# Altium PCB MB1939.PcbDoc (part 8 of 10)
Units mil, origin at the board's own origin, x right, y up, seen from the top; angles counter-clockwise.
Board outline 5910.64 x 4335.93 mil, 6 copper layers (Top Layer, l2_GND, L3_SIG, L4_VCC, L5_GND, Bottom Layer), stack 58.424 mil thick; 635 components, 489 nets, 2289 pads, 1388 vias.
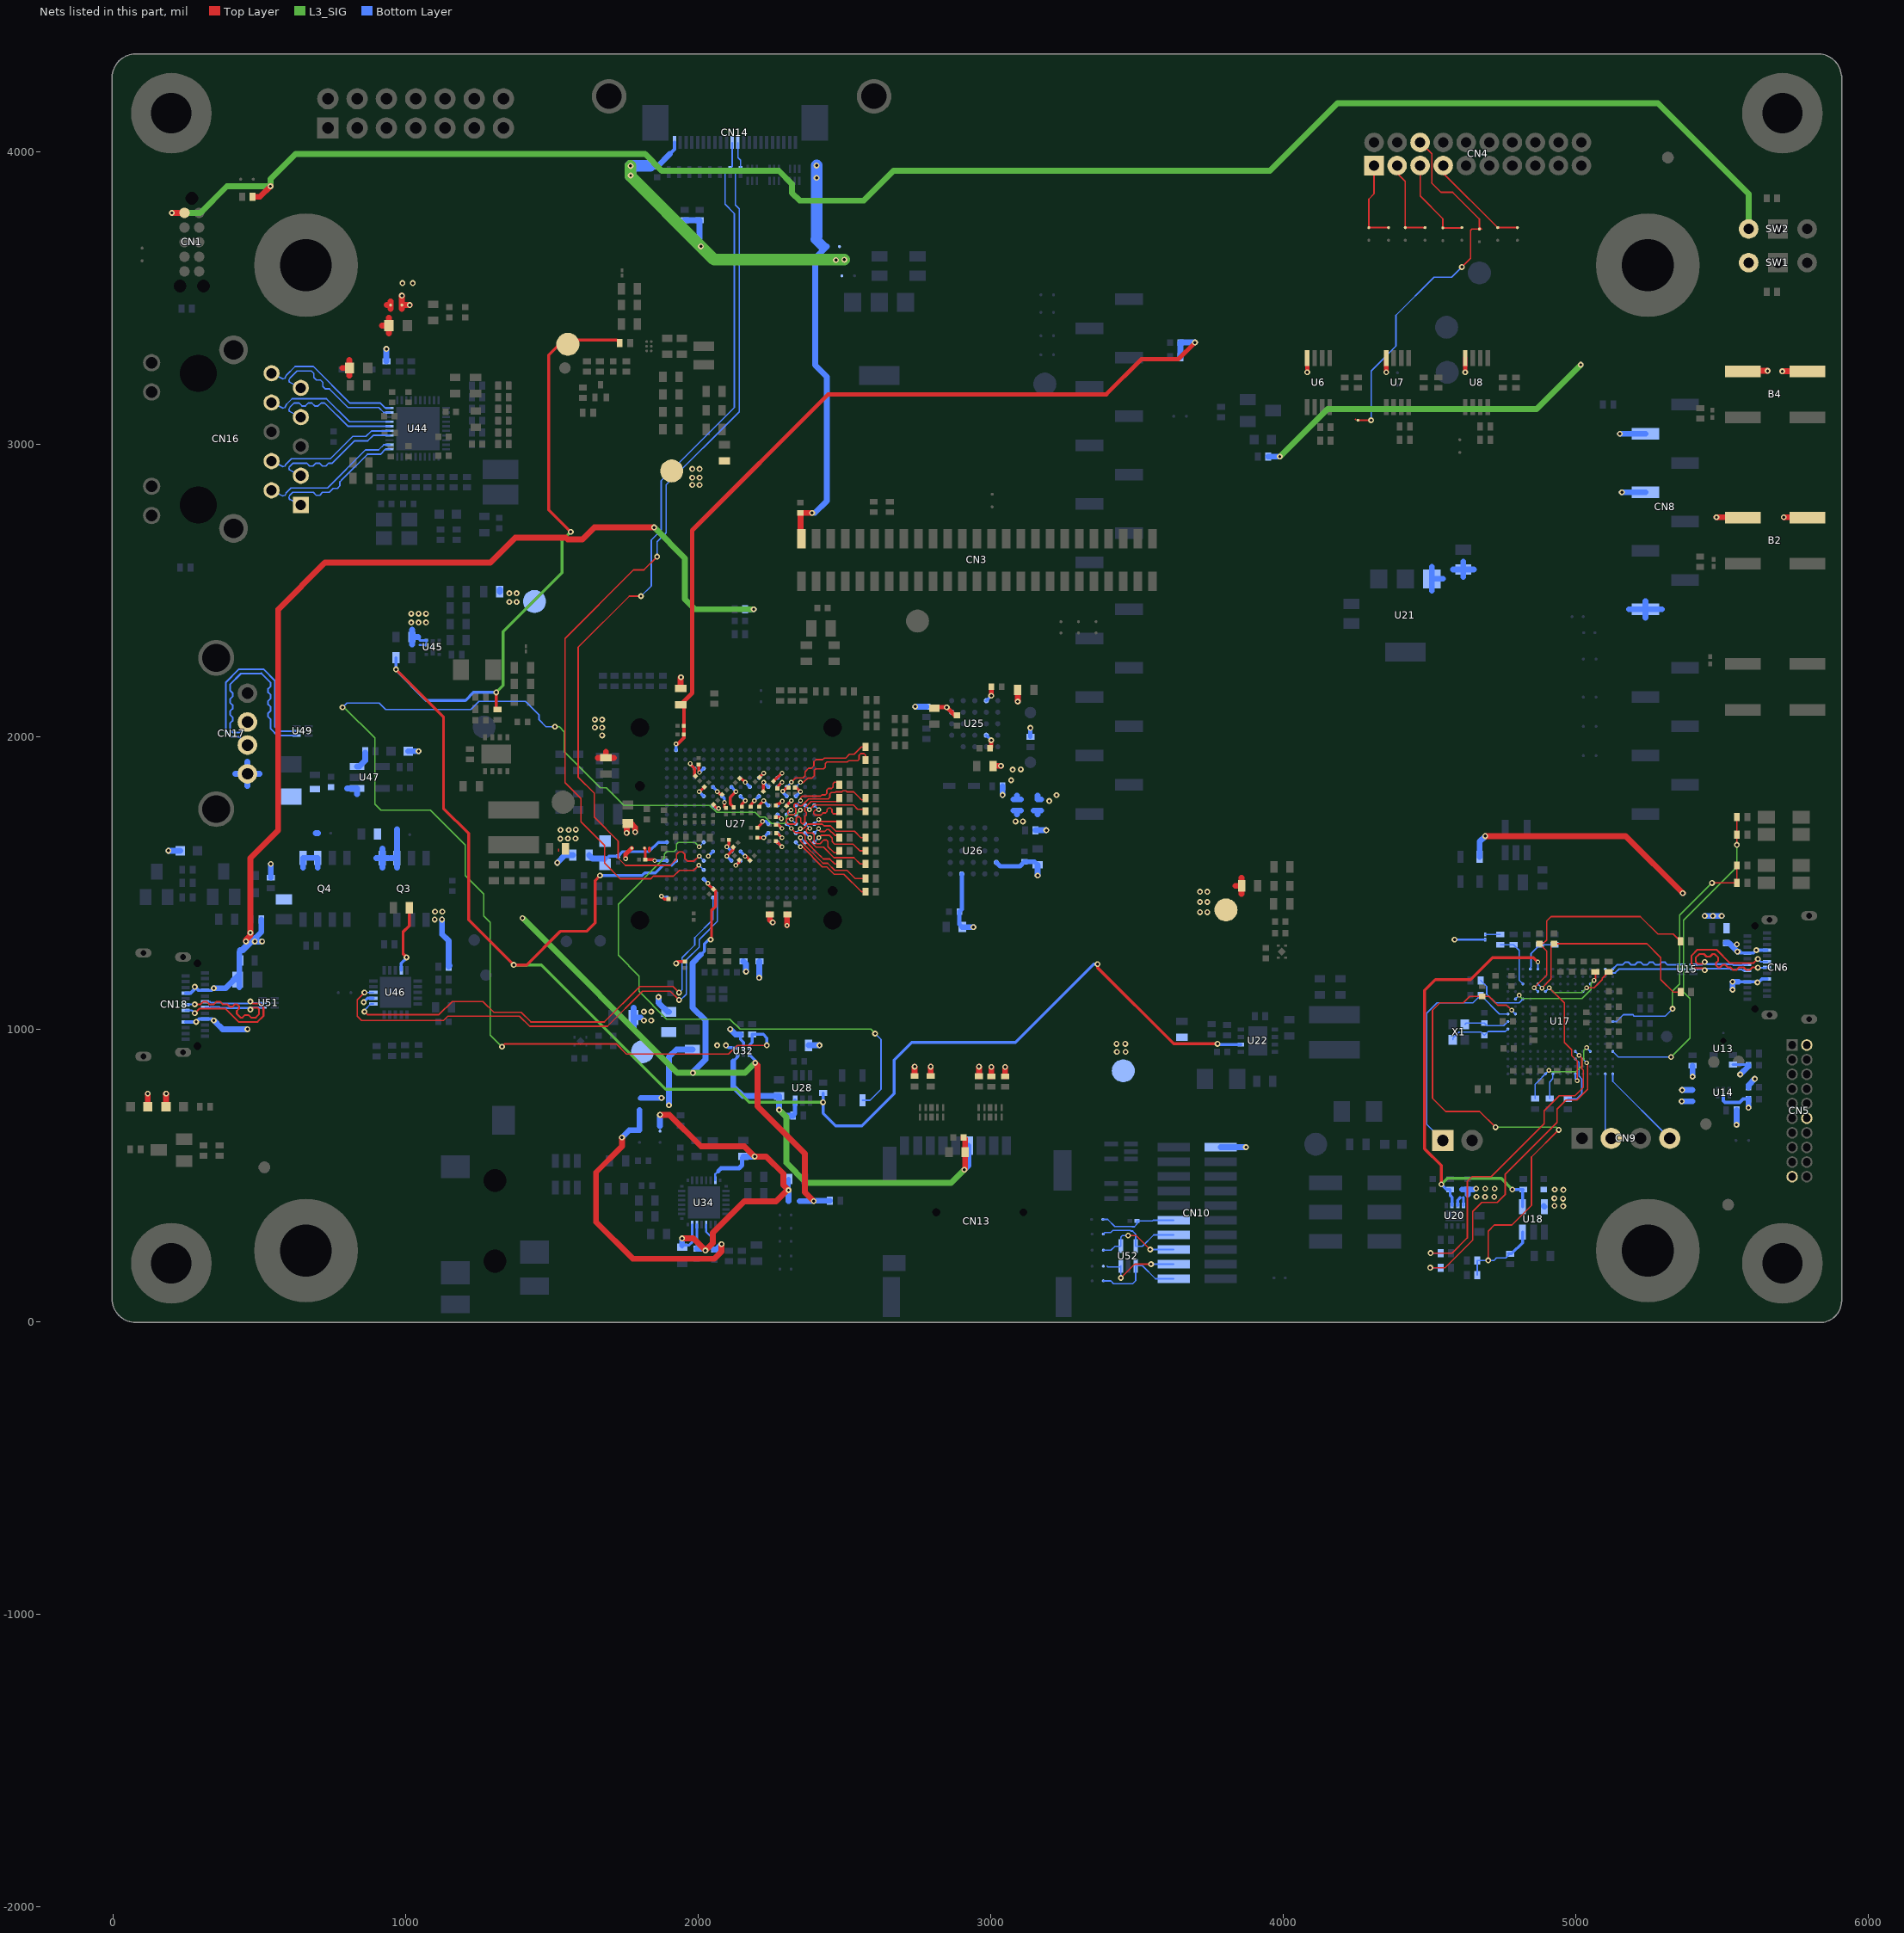
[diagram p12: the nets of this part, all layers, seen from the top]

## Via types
v1: diameter 20, hole 10, Top Layer to Bottom Layer, tented both sides, 1072 vias
v2: diameter 16, hole 8, Top Layer to Bottom Layer, tented both sides, 316 vias

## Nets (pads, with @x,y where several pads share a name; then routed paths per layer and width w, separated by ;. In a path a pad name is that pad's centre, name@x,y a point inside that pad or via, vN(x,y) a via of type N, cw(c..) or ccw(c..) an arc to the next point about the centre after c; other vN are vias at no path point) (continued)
PO5: R150.2 U27.K15 U32.6 | length 4418
  Top Layer w5: v1(1330,940) 1340,950 1720,950 1755,915 2104,915 2134,945 v1(2235,945)
  L3_SIG w4: v1(785,2100) 790,2100 895,1995 895,1770 915.73,1749.27 1085.73,1749.27 1205,1630 1205,1525 1268,1462 1268,1387 1290,1365 1290,980 v1(1330,940) ; v1(1511,2034) 1526,2034 1543,2017 1543,1948.37 1665.68,1825.69 1686.31,1825.69 1747,1765 2040,1765 2064,1741 2194.9,1741 2210.9,1725 2229,1725 2251,1703 2295.46,1703 2301.46,1709 2301.46,1726.13 2309.33,1734 2334.76,1734 v2(2349.15,1748.39)
  Bottom Layer w5: v1(785,2100) 800,2115 910,2115 932.5,2092.5 1223.9,2092.5 1251.9,2120.5 1409.8,2120.5 1456.75,2073.55 1456.75,2057.25 1480,2034 v1(1511,2034) ; U27.K15@2334.32,1733.56 v2(2349.15,1748.39)
  Bottom Layer w10: U32.6@2174.67,936.81 2174.67,944.67 2185,955 R150.2@2185,982.28 2222.72,982.28 2235,970 v1(2235,945)
PP0: R56.2 U27.G17 | length 213.9
  Top Layer w5: v2(2412.97,1654.77) 2421.2,1663 2448,1663 2458,1653 2458,1640.99 2466.36,1632.63 2529.52,1632.63 2545.87,1616.28 2546.16,1616.28 2552.44,1610 R56.2@2572.29,1610
  Bottom Layer w5: U27.G17@2397.32,1639.02 2397.31,1639.11 v2(2412.97,1654.77)
PP1: R55.2 U27.H16 | length 256.8
  Top Layer w5: v2(2381.51,1654.79) 2381.51,1643.49 2403,1622 2428.53,1622 2464.25,1586.28 2532.72,1586.28 2554,1565 R55.2@2572.29,1565
  Bottom Layer w5: U27.H16@2365.82,1670.51 v2(2381.51,1654.79)
PP2: R47.2 U27.J17 | length 98.2
  Top Layer w5: v2(2412.14,1716.9) 2419.04,1710 2472.28,1710 R47.2@2482.29,1700
  Bottom Layer w5: U27.J17@2397.32,1702.01 2412.14,1716.84 v2(2412.14,1716.9)
PP3: R45.2 U27.J16 | length 220.5
  Top Layer w5: v2(2381.51,1686.29) 2375.04,1686.29 2370.04,1681.29 2370.04,1675.79 2375.04,1670.79 2391.21,1670.79 2397,1665 2397,1642.01 2404.5,1634.51 2417,1634.51 2429.2,1646.71 2439,1646.71 2444,1641.71 2444,1624 2465,1603 2475.28,1603 R45.2@2482.29,1610
  Bottom Layer w5: U27.J16@2365.82,1702.01 v2(2381.51,1686.29)
PP4: R57.2 U27.H15 | length 269.5
  Top Layer w5: v2(2349.55,1685.79) 2359.79,1685.79 2374.79,1700.79 2424.22,1700.79 2430.01,1695 2452,1695 2470.72,1676.28 2535,1676.28 2556.28,1655 R57.2@2572.29,1655
  Bottom Layer w5: U27.H15@2334.32,1670.56 v2(2349.55,1685.79)
PP5: R44.2 U27.J14 | length 246.8
  Top Layer w5: v2(2318.52,1686.3) 2333.53,1671.29 2356.24,1671.29 2365.52,1662.01 2365.52,1643.99 2416.51,1593 2417.01,1593 2427.99,1582.02 2450,1582.02 2467.02,1565 R44.2@2482.29,1565
  Bottom Layer w5: U27.J14@2302.83,1702.01 v2(2318.52,1686.3)
PP6: R54.2 U27.G16 | length 308.9
  Top Layer w5: v2(2349.99,1654.73) 2349.99,1643.83 2426.81,1567.01 2443,1567.01 2467.01,1543 2509,1543 2537,1515 R54.2@2572.29,1515
  Bottom Layer w5: v2(2349.99,1654.73) 2365.7,1639.02 U27.G16@2365.82,1639.02
PP7: R53.2 U27.G15 | length 308
  Top Layer w5: v2(2350.02,1623.29) 2356.7,1623.29 2424.99,1555 2440,1555 2465,1530 2498,1530 2558,1470 R53.2@2572.29,1470
  Bottom Layer w5: U27.G15@2334.33,1639.02 v2(2350.02,1623.29)
PP8: R59.2 U27.L16 | length 228.2
  Top Layer w5: v2(2380.64,1750.11) 2396.78,1766.25 2504.54,1766.25 ; 2504.57,1766.28 2531.16,1766.28 2545.44,1752 2565.28,1752 R59.2@2572.29,1745
  Bottom Layer w5: U27.L16@2365.82,1765 2365.82,1764.93 v2(2380.64,1750.11)
PP9: R64.2 U27.N14 | length 342
  Top Layer w5: v2(2318.91,1844.34) 2319.16,1844.34 2333.83,1859.01 2358,1859.01 2365.52,1866.53 2365.52,1880.01 2377.39,1891.88 2386.45,1891.88 2386.83,1892.26 2387.47,1892.26 2395.96,1900.75 2395.96,1913.95 2403.27,1921.26 2426.25,1921.26 2431.99,1927 2504.5,1927 2517.5,1940 2533,1940 2558,1965 R64.2@2572.29,1965
  Bottom Layer w5: U27.N14@2302.83,1827.99 2318.91,1844.09 v2(2318.91,1844.34)
PP10: R63.2 U27.N15 | length 330
  Top Layer w5: v2(2350.02,1843.7) 2359.32,1843.7 2363.32,1847.7 2374.32,1858.01 2375.19,1858.01 2375.45,1858.27 2389.27,1858.27 2397.52,1866.52 2397.52,1885 2402.52,1890 2429,1890 2435,1896 2435,1908 2440,1913 2510,1913 2515,1918 2546,1918 2550.11,1922.11 2550.11,1935.89 2556.22,1942 2567.28,1942 2572.28,1937 R63.2@2572.29,1920
  Bottom Layer w5: U27.N15@2334.33,1827.99 v2(2350.02,1843.7)
PP11: R50.2 U27.L15 | length 206.5
  Top Layer w5: v2(2350.24,1780.98) 2350.24,1791.38 2355.25,1796.39 2418.38,1796.39 2422.99,1801 2435,1801 2440,1806 2440,1818 2445,1823 2455.99,1823 2460.99,1828 2460.99,1839 2466.09,1844.1 2477.28,1844.1 2482.28,1839.1 R50.2@2482.29,1835
  Bottom Layer w5: U27.L15@2334.33,1765 2334.32,1765.06 v2(2350.24,1780.98)
PP12: R49.2 U27.J15 | length 346.3
  Top Layer w5: v2(2319.14,1717.13) 2316.1,1720.17 2306.46,1720.17 2301.46,1715.17 2301.46,1706 2306.46,1701 2331,1701 2335.46,1705.46 2335.46,1722.54 2338.92,1726 2346,1726 2351,1721 2351,1706.66 2355,1702.66 2360.66,1702.66 2365,1707 2365,1728 2369.96,1732.96 2369.96,1740.04 2365,1745 2365,1756.49 2386.52,1778.01 2477.28,1778.01 2482.28,1783.01 R49.2@2482.29,1790
  Bottom Layer w5: v2(2319.14,1717.13) U27.J15@2334.33,1702.01 U27.J15@2334.33,1702.01
PP13: R60.2 U27.K14 | length 396.1
  Top Layer w5: v2(2317.65,1748.39) 2311.47,1748.39 2306.92,1743.84 2306.92,1737.41 2311.46,1732.87 2329,1732.87 2334,1737.87 2334,1754.01 2328.05,1759.96 2328.05,1767.05 2331.96,1770.96 2339.04,1770.96 2346.45,1763.55 2353.54,1763.55 2377,1787.01 2445,1787.01 2450,1792.01 2450,1804 2455,1809 2468.08,1809 2470.36,1811.28 2491.28,1811.28 2495,1815 2505,1815 2508.72,1811.28 2531.71,1811.28 2554,1788.99 2554,1788.91 2559.01,1783.9 2567.28,1783.9 2572.28,1788.9 R60.2@2572.29,1790
  Bottom Layer w5: U27.K14@2302.82,1733.56 v2(2317.65,1748.39)
PP14: R48.2 U27.L17 | length 170.5
  Top Layer w5: v2(2412.14,1750.11) 2401.95,1750.11 2395.46,1743.62 2395.46,1736.54 2400,1732 2420,1732 2427,1739 2435.69,1739 2440.67,1743.98 2440.67,1751.02 2445.65,1756 2452.69,1756 2457.67,1751.02 2457.67,1741 2462.67,1736 2477.28,1736 2482.28,1741 R48.2@2482.29,1745
  Bottom Layer w5: U27.L17@2397.32,1765 2397.31,1764.94 v2(2412.14,1750.11)
PP15: R46.2 U27.H17 | length 111.7
  Top Layer w5: v2(2411.98,1685.24) 2411.98,1681.16 2416.99,1676.15 2433.15,1676.15 2439.96,1682.96 2447.04,1682.96 2467,1663 2474.28,1663 R46.2@2482.29,1655
  Bottom Layer w5: U27.H17@2397.32,1670.51 2397.31,1670.57 v2(2411.98,1685.24)
PQ0: CN14.12 U27.E5 U35.1 | length 3142.1
  Top Layer w5: v1(1805,2480) 1765,2480 1590,2305 1590,1861.66 1645,1806.66 1645,1725 1727.08,1642.92 1727.08,1584.92 1752,1560 1905.01,1560 1926.1,1581.09 1926.1,1597.83 1934.59,1606.32 1946.61,1606.32 1955.1,1597.83 1955.1,1582.62 1962.9,1574.82 1986.83,1574.82 v2(2003.7,1591.69)
  Bottom Layer w5: v1(1805,2480) 1840,2515 1840,2672 1874,2706 1874,2875 2124,3125 2124,3788.02 2092.02,3820 2092.02,3925.89 2092.5,3926.37 2092.5,3932.5 2102.3,3942.3 U35.1@2110,3942.31 2116.46,3948.76 CN14.12@2116.46,4030.71 ; v2(2003.7,1591.69) U27.E5@2019.36,1576.03
PQ5: CN14.11 U27.D5 U33.1 | length 3191.2
  Top Layer w5: v1(1860,2615) 1815,2570 1780,2570 1545,2335 1545,1843 1600,1788 1600,1709 1680.78,1628.22 1680.78,1567.56 1734.34,1514 1838,1514 1847,1523 1916.19,1523 1936.19,1543 1938.01,1543 1938.31,1543.3 1985.31,1543.3 v2(2002.95,1560.94)
  Bottom Layer w5: v1(1860,2615) 1860,2666 1891,2697 1891,2861 2140.5,3110.5 2140.5,3804.16 2127.76,3816.9 2127.76,3926.63 2137.33,3936.2 2140,3936.2 2145,3941.2 U33.1@2145,3942.31 2145,3970 2136.14,3978.86 CN14.11@2136.15,4030.71 ; v2(2002.95,1560.94) U27.D5@2019.36,1544.53
PQ7: D5.2 U27.G5 | length 1880.9
  L3_SIG w4: v2(2003.59,1623.23) 1988.82,1638 1932,1638 1926,1632 1926,1615 1919,1608 1893.86,1608 1885,1599.14 1885,1585 1727.1,1427.1 1727.1,1252.9 1798,1182 1798,1130.03 1893.03,1035 2108.02,1035 2143.02,1000 2590,1000 v1(2605,985)
  Bottom Layer w5: v2(2003.59,1623.23) U27.G5@2019.36,1639.02 ; D5.2@2562.01,757.36 2587.37,757.36 2625,794.99 2625,965 v1(2605,985)
PWR_ON: R12.1 R25.1 R144.1 R199.1 TP11.1 U22.2 U27.E2 | length 7204.2
  Top Layer w10: v1(967.44,2230) 1130,2067.44 1130,1755 1216,1669 1216,1374 v1(1370,1220) 1415,1220 1530,1335 1620,1335 1648,1363 1648,1508 v1(1665,1525) ; v1(1310,2151) 1310,2097.72 R12.1@1315,2092.72 ; v1(1565,2700) 1490,2775 1490,3304 1541,3355 1722.28,3355 R25.1@1732.28,3345 ; v1(3365,1222.5) 3365,1210 3625,950 v1(3775,950)
  L3_SIG w10: v1(1310,2151) 1334,2175 1334,2359 1535,2560 1535,2670 v1(1565,2700) ; v1(1370,1220) 1465,1220 1890,795 2130,795 2175,750 v1(2427.01,750)
  Bottom Layer w8: 1875,1555 1880.62,1560.62 1909.46,1560.62
  Bottom Layer w10: R199.1@967.45,2270 v1(967.44,2230) 967.44,2227.56 1071,2124 1205.2,2124 1232.2,2151 v1(1310,2151) ; v1(1665,1525) 1809,1525 1818,1534 1854,1534 1875,1555 ; 1909.46,1560.62 U27.E2@1924.88,1576.03 ; R144.1@2427.01,781.77 v1(2427.01,750) 2427.01,712.99 2470,670 2560,670 2670,780 2670,895 2730,955 3085,955 3352.5,1222.5 v1(3365,1222.5) ; v1(3775,950) 3777.29,947.71 U22.2@3854.92,947.71
RJ45_D1_N: CN16.2 U44.2 | length 482.1
  Bottom Layer w5.1: CN16.2@542.49,2841.8 581.2,2822.44 588.05,2824.73 592.35,2833.36 608.99,2850 733.78,2850 863.78,2980 908.27,2980 925.98,2997.71 U44.2@946.18,2997.71
RJ45_D1_P: CN16.1 U44.1 | length 480.7
  Bottom Layer w5.1: CN16.1@642.49,2791.8 603.73,2811.18 601.47,2818.02 604.69,2824.47 615.21,2834.99 685.2,2835 695,2825.2 707,2825.2 716.8,2835 740,2835 753.52,2848.52 767.39,2848.52 775.88,2857.01 775.88,2870.88 784.36,2879.36 ; 784.39,2879.36 870,2965 914.49,2965 931.45,2981.96 U44.1@946.18,2981.96
RJ45_D2_N: CN16.4 U44.5 | length 459.6
  Bottom Layer w5.1: CN16.4@542.49,2941.8 581.2,2922.44 588.05,2924.73 590.84,2930.33 610.11,2949.6 743.48,2949.6 819.98,3026.1 865.32,3026.1 883.79,3044.57 945.78,3044.57 U44.5@946.18,3044.96
RJ45_D2_P: CN16.3 U44.4 | length 458.5
  Bottom Layer w5.1: CN16.3@642.49,2891.8 603.73,2911.18 601.47,2918.02 603.18,2921.45 616.33,2934.6 662.5,2934.6 672.3,2924.8 684.3,2924.8 694.1,2934.6 706.1,2934.6 715.9,2924.8 727.9,2924.8 737.7,2934.6 749.7,2934.6 826.2,3011.1 871.54,3011.1 890.01,3029.57 945.81,3029.57 U44.4@946.18,3029.21
RJ45_D3_N: CN16.8 U44.7 | length 456.3
  Bottom Layer w5.1: CN16.8@542.49,3141.8 581.2,3122.44 588.05,3124.73 593.55,3135.76 612.79,3155 730,3155 808.93,3076.07 921.24,3076.07 921.62,3076.45 U44.7@946.17,3076.45
RJ45_D3_P: CN16.7 U44.6 | length 455.2
  Bottom Layer w5.1: CN16.7@642.49,3091.8 603.73,3111.18 601.47,3118.02 605.89,3126.87 619.01,3140 636.58,3140 646.38,3130.2 658.38,3130.2 668.18,3140 680.18,3140 689.98,3130.2 701.98,3130.2 711.78,3140 723.78,3140 802.71,3061.07 921.24,3061.07 921.61,3060.7 U44.6@946.18,3060.7
RJ45_D4_N: CN16.10 U44.10 | length 486
  Bottom Layer w5.1: CN16.10@542.49,3241.8 581.2,3222.44 588.05,3224.73 593.33,3235.32 623.01,3265 685,3265 810.09,3139.91 915.08,3139.91 931.29,3123.7 U44.10@946.18,3123.7
RJ45_D4_P: CN16.9 U44.9 | length 485.3
  Bottom Layer w5.1: CN16.9@642.49,3191.8 603.73,3211.18 601.47,3218.02 605.67,3226.43 629.23,3250 678.78,3250 687.26,3241.52 687.26,3227.65 695.75,3219.17 709.61,3219.17 718.09,3210.69 718.09,3196.82 726.58,3188.34 740.44,3188.34 803.87,3124.91 908.86,3124.91 925.82,3107.95 U44.9@946.18,3107.95
STLK_LED: R100.2 R101.1 U17.D15 | length 1138.5
  Top Layer w5: v1(5550,1630) R101.1@5550.01,1725
  L3_SIG w4: v1(5325,905) 5390,970 5390,1105 5368,1127 5368,1373 5550,1555 v1(5550,1630)
  Bottom Layer w5: U17.D15@5125.83,924.06 5144.88,905 v1(5325,905)
STLK_NRST: C130.2 JP1.1 U17.J1 | length 787.5
  Bottom Layer w5: JP1.1@4545,620 4490,675 4490,1055 4525,1090 4647.99,1090 C130.2@4674.41,1116.42 4738.82,1052.01 U17.J1@4767.56,1052.01
STLK_OSC_IN: C127.1 U17.G1 X1.1 | length 216.2
  Bottom Layer w5: X1.1@4579.34,963.42 4579.33,969.33 4600,990 4675.83,990 C127.1@4686.69,979.14 4699.94,992.39 4759.12,992.39 U17.G1@4767.56,1000.83
STLK_OSC_OUT: C128.2 U17.H1 X1.3 | length 158.1
  Bottom Layer w5: X1.3@4620.67,1016.57 4625.08,1020.98 C128.2@4686.69,1020.98 4695.28,1012.39 4753.53,1012.39 U17.H1@4767.56,1026.42
STLK_SWCLK: CN9.2 U17.A14 | length 228.7
  Bottom Layer w5: U17.A14@5100.24,847.29 5100.23,647.29 CN9.2@5120.51,627.01
STLK_SWDIO: CN9.4 U17.A15 | length 300.9
  Bottom Layer w5: U17.A15@5125.83,847.29 5125.82,821.7 CN9.4@5320.51,627.01
STLK_UCPD_CC1_C: C103.1 R96.1 U17.M5 | length 791.1
  Top Layer w5: v2(4856.85,1141.85) 4900,1185 4900,1267.28 C103.1@4875,1292.28 4887.28,1292.28 4900,1305 4900,1370 4915,1385 5220,1385 5280,1325 5332.28,1325 R96.1@5357.29,1300
  Bottom Layer w5: v2(4856.85,1141.85) U17.M5@4869.92,1128.78
STLK_UCPD_CC2_C: C105.1 R97.1 U17.N5 | length 734
  Top Layer w5: v2(4883.54,1140.75) 4915,1172.21 4915,1283.78 4923.5,1292.28 5242.72,1292.28 5290,1245 5290,1170 5332.99,1127.01 R97.1@5357.8,1127.01
  Bottom Layer w5: U17.N5@4869.92,1154.37 v2(4883.54,1140.75)
STLK_USB_CN_N: CN6.A7 CN6.B7 U15.2 | length 567.7
  Top Layer w6.1: v1(5440,1202) 5433.5,1208.5 5409.88,1208.5 5395,1223.38 5395,1251.74 5415.26,1272 5479.91,1272 5525.41,1226.5 5607.74,1226.5 v1(5621.35,1240.11)
  Bottom Layer w6.1: U15.2@5401.67,1205 5402.42,1205.75 5436.25,1205.75 v1(5440,1202) 5445.39,1207.39 5527.61,1207.39 5531.32,1203.68 5566.78,1203.68 5569.12,1201.33 CN6.A7@5585.95,1201.33 ; v1(5621.35,1240.11) 5629.4,1232.06 5630.44,1232.06 5631.64,1230.86 CN6.B7@5652.88,1230.86
STLK_USB_CN_P: CN6.A6 CN6.B6 U15.1 | length 567.4
  Top Layer w6.1: v1(5440,1230) 5433.5,1223.5 5416.1,1223.5 5410,1229.6 5410,1245.53 5421.47,1257 5437.3,1257 5446.1,1248.2 5458.1,1248.2 5466.9,1257 5473.7,1257 5486.32,1244.38 5486.32,1234.29 5478.51,1226.48 5478.51,1218.12 5484.61,1212.02 5493.25,1212.02 5501.36,1220.13 5510.57,1220.13 5519.2,1211.5 5527.61,1211.5 5536.41,1202.7 5548.41,1202.7 5557.21,1211.5 5573.04,1211.5 5581.84,1202.7 5593.84,1202.7 5602.64,1211.5 5619.96,1211.5 v1(5621.35,1210.11)
  Bottom Layer w6.1: U15.1@5401.67,1220.75 5430.75,1220.75 v1(5440,1230) 5447.61,1222.39 5533.82,1222.39 5537.54,1218.68 5566.78,1218.68 5569.12,1221.02 CN6.A6@5585.95,1221.02 ; v1(5621.35,1210.11) 5651.81,1210.11 CN6.B6@5652.88,1211.18
STLK_USB_N: U15.5 U17.R14 | length 270.7
  Bottom Layer w6.1: U17.R14@5100.23,1205.55 5113.21,1192.57 5134.06,1192.57 5146.49,1205 5360.08,1205 U15.5@5360.33,1205.25
STLK_USB_P: U15.6 U17.R15 | length 270
  Bottom Layer w6.1: U17.R15@5125.82,1205.55 5140.27,1220 5159.2,1220 5168,1228.8 5180,1228.8 5188.8,1220 5200.8,1220 5209.6,1228.8 5221.6,1228.8 5230.4,1220 5242.4,1220 5251.2,1228.8 5263.2,1228.8 5272,1220 5284,1220 5292.8,1228.8 5304.8,1228.8 5313.6,1220 5359.58,1220 U15.6@5360.33,1220.75
STLK_VCP_RX: R112.1 U17.C10 | length 183.6
  Bottom Layer w5: R112.1@4971.69,761.42 5001.41,761.42 5020,780.01 5020,830 5010,840 5010,886.34 U17.C10@4997.88,898.47
STLK_VCP_TX: R114.1 U17.A7 | length 89.2
  Bottom Layer w5: R114.1@4910,762.72 4910,819.99 4921.1,831.09 U17.A7@4921.1,847.29
STMOD_ADC: CN4.13 SB9.2 SB16.1 | length 1317.2
  Top Layer w4: CN4.13@4467.52,4030.71 4506.9,3991.33 4506.9,3892.1
  Top Layer w5: 4245.51,3083.39 4247.12,3085 ; SB9.2@4255,3081.38 v1(4300,3081.38) ; 4506.9,3892.1 4538.6,3860.4 4578.6,3860.4 4669.8,3769.2 4669.8,3742 4677.12,3734.68 4644.68,3734.68 4640,3730 4640,3635 v1(4610,3605)
  Bottom Layer w5: v1(4300,3081.38) 4300,3250 4385,3335 4385,3440 4515,3570 4575,3570 v1(4610,3605)
STMOD_MISO5/RX: CN4.3 SB14.2 SB15.2 | length 285.3
  Top Layer w5: CN4.3@4467.52,3926.26 4467.52,3847.48 4545,3770 SB14.2@4545,3738.62 4608.62,3738.62 SB15.2@4610,3740
STMOD_MOSI5/TX: CN4.2 SB12.2 SB13.2 | length 265.5
  Top Layer w5: CN4.2@4388.78,3926.26 4416.81,3898.23 SB12.2@4416.81,3739.68 SB13.2@4484.13,3739.68
STMOD_NSS/CTS: CN4.1 SB10.2 SB11.2 | length 261.3
  Top Layer w5: CN4.1@4310.04,3926.26 4310.04,3855 4292.17,3837.13 SB10.2@4292.17,3739.68 SB11.2@4359.49,3739.68
STMOD_SCK/RTS: CN4.4 SB17.2 SB18.2 | length 331.2
  Top Layer w5: CN4.4@4546.26,3926.26 SB17.2@4732.52,3740 ; SB17.2@4732.52,3739.68 SB17.2@4732.52,3740 ; SB18.2@4799.84,3739.68 4732.84,3739.68 SB17.2@4732.52,3740
T_JTDI: R122.1 U17.L3 | length 196.6
  Bottom Layer w5: R122.1@4674.41,1166.42 4695,1145.83 4695,1120 4725,1090 4805.55,1090 U17.L3@4818.74,1103.19
T_PWR_EN: R118.2 R125.2 U17.R5 U18.4 U20.2 | length 1608.8
  Top Layer w10: v1(4540,470) 4540,534 4483,591 4483,1133 4520,1170 4640,1170 4715,1245 4854.92,1245 v2(4869.92,1230)
  L3_SIG w10: v1(4540,470) 4560,490 4745,490 v1(4782.72,452.28)
  Bottom Layer w5: U17.R5@4869.92,1205.55 v2(4869.92,1230)
  Bottom Layer w10: v1(4540,470) 4557.72,452.28 R125.2@4570,452.28 4570,432.24 4576.14,426.1 U20.2@4576.14,397.87 ; v1(4782.72,452.28) R118.2@4820,452.28 4817.6,449.88 U18.4@4817.6,393.31
T_PWR_EXT: R113.1 R115.1 U17.R4 | length 146.6
  Bottom Layer w5: U17.R4@4844.33,1205.55 4844.33,1211.42 4846.69,1213.78 4846.69,1258.7 R115.1@4876.69,1288.7 R113.1@4926.69,1288.7
T_PWR_INT: C33.1 R120.2 R123.1 R124.2 U17.J2 U18.3 | length 1958.3
  Top Layer w5: v1(4700,210) 4700,310 4721,331 4781,331 4848,398 4848,563 v1(4941,656) ; v1(4725,665) 4671,719 4555,719 4510,764 4510,1065 4535,1090 4615,1090 4637.28,1112.28 C33.1@4680,1112.28 4702.72,1112.28 4732.84,1082.16 4763,1082.16 v2(4780.37,1064.79)
  L3_SIG w4: v1(4725,665) 4932,665 v1(4941,656)
  Bottom Layer w5: R123.1@4662.72,160 R124.2@4662.72,210 v1(4700,210) 4720,210 4728,218 4760.28,218 R120.2@4775,232.72 ; v2(4780.37,1064.79) U17.J2@4793.15,1052.01
  Bottom Layer w10: R120.2@4768.38,232.72 4780.02,232.72 4817.6,270.3 U18.3@4817.6,306.69
T_PWR_LED: R98.2 R99.2 U17.H15 | length 857.3
  Top Layer w5: v1(5465,1500) R98.2@5550.01,1500 R99.2@5550.01,1560
  L3_SIG w4: v1(5330,1070) 5330,1130 5355,1155 5355,1390 v1(5465,1500)
  Bottom Layer w5: U17.H15@5125.83,1026.42 5139.1,1026.42 5162.68,1050 5193.74,1050 5198.74,1045 5305,1045 v1(5330,1070)
T_PWR_SEL1: R127.2 U17.D10 | length 1063.7
  Top Layer w5: v1(4503,235) 4577,235 4629,287 4629,480 4645,496 4710,496 4891,677 4891,720.99 4942.5,772.5 4996.28,772.5 5025,801.22 5025,860 5020,865 5020,901.93 v2(5010.97,910.96)
  Bottom Layer w5: v1(4503,235) R127.2@4537.29,235 ; U17.D10@4997.88,924.06 v2(5010.97,910.96)
T_PWR_SEL2: R126.2 U17.C11 | length 1060.3
  Top Layer w5: v1(4502.1,185) 4552.52,185 4647,279.48 4647,377 4678,408 4731,408 4758,435 4758,504 4935,681 4935,726.61 4965.89,757.5 5002.5,757.5 5040,795 5040,881.27 v2(5036.27,885)
  Bottom Layer w5: v1(4502.1,185) R126.2@4537.29,185 ; U17.C11@5023.47,898.47 5036.27,885.66 v2(5036.27,885)
T_SWCLK: R95.1 U17.A10 U17.M6 U17.M11 | length 661.4
  Top Layer w5: v2(4908.29,1141.57) 4960,1089.86 4960,955 4985,930 4985,910 5004.03,890.97 v2(5004.03,824.03) ; v2(5036.24,1141.57) 5061.57,1141.57 5090,1170 5090,1174.29 R95.1@5111.69,1195.98
  L3_SIG w4: v2(4908.29,1141.57) 4924.86,1125 5019.67,1125 v2(5036.24,1141.57)
  Bottom Layer w5: U17.M6@4895.51,1128.78 v2(4908.29,1141.57) ; U17.A10@4997.88,847.29 4997.87,830.19 v2(5004.03,824.03) ; U17.M11@5023.47,1128.78 v2(5036.24,1141.57)
T_SWDIO: R94.1 U17.L2 U17.N12 | length 365.6
  Top Layer w5: v2(5061.83,1167.16) 5066.69,1172.02 R94.1@5066.69,1195.98
  L3_SIG w4: v2(4805.93,1115.97) 4816.9,1105 4824.94,1105 4825.31,1105.37 4876.46,1105.37 ; 4876.48,1105.39 5021.28,1105.39 5051.24,1135.35 5051.24,1147.79 ; 5051.22,1147.81 5051.22,1156.55 v2(5061.83,1167.16)
  Bottom Layer w5: U17.L2@4793.15,1103.19 v2(4805.93,1115.97) ; U17.N12@5049.05,1154.38 v2(5061.83,1167.16)
T_SWO: R116.1 U17.A6 U17.D12 | length 325.5
  L3_SIG w4: v2(4907.5,859.24) 4911.74,855 5000,855 5020.77,875.77 5020.77,891.43 5026.47,897.13 5026.47,927.07 v2(5036.27,936.87)
  Bottom Layer w5: R116.1@4860,762.72 4860,811.78 v2(4907.5,859.24) ; v2(5036.27,936.87) U17.D12@5049.05,924.09
T_VCC: LNK3.2 R121.2 | length 51.8
  Bottom Layer w5: LNK3.2@4690,1323.86 4690.28,1324.14 R121.2@4741.69,1324.14
T_VCC_AIN: R119.1 R121.1 U17.N3 | length 192.6
  Bottom Layer w5: R121.1@4741.69,1288.7 R119.1@4786.69,1288.7 4805.91,1269.48 4805.91,1167.2 U17.N3@4818.74,1154.37
TRACE_CLK: CN10.12 SB29.1 U53.1 | length 268
  Bottom Layer w5: SB29.1@3383.39,350 3400,350 3424.5,325.5 3482.63,325.5 3483.13,325 3490.83,325 3500,334.17 U53.1@3500,345 3552.99,345 3555,347.01 CN10.12@3625.53,347.01
TRACE_D0: CN10.14 SB30.1 U52.5 | length 308
  Bottom Layer w5: SB30.1@3385,300 3390,305 3410,305 3417.5,312.5 3477.25,312.5 3479.75,310 3485,310 3495.59,299.41 U52.5@3495.59,258.46 3518.46,258.46 3557.01,297.01 CN10.14@3625.53,297.01
TRACE_D1: CN10.16 SB26.1 U52.4 | length 299.2
  Top Layer w5: v1(3470,295) 3497.01,295 v1(3545,247.01)
  Bottom Layer w5: SB26.1@3385,245 3411.26,245 3424.72,258.46 U52.4@3444.41,258.46 3444.41,289.41 3450,295 v1(3470,295) ; v1(3545,247.01) CN10.16@3625.53,247.01
TRACE_D2: CN10.18 SB28.1 U52.3 | length 289.9
  Top Layer w5: v1(3445,150) 3492.01,197.01 v1(3547.99,197.01)
  Bottom Layer w5: 3397.8,190 3399.92,187.87 U52.3@3445,187.87 ; U52.3@3444.41,191.54 3445,190.94 U52.3@3445,187.87 ; v1(3445,150) U52.3@3445,187.87 ; v1(3547.99,197.01) CN10.18@3625.53,197.01
TRACE_D3: CN10.20 SB27.1 U52.1 | length 318.4
  Bottom Layer w5: SB27.1@3385,140 3410,140 3420,130 3485,130 3495.59,140.59 U52.1@3495.59,191.54 3518.46,191.54 3562.99,147.01 CN10.20@3625.53,147.01
UCPD1_CC1: U27.A6 U46.1 | length 1602.7
  Top Layer w5: v1(860,1060) 870,1050 1115,1050 1160,1095 1265,1095 1302,1058 1395.38,1058 1428.38,1025 1680,1025 1800.97,1145.97 1914.03,1145.97 v1(1935,1125)
  Bottom Layer w5: v1(860,1060) 860,1065 881.33,1086.33 U46.1@890.23,1086.33 ; v1(1935,1125) 1945,1135 1945,1244 1988.72,1287.72 1988.72,1312.72 2050.86,1374.86 U27.A6@2050.86,1450.04
UCPD1_CC2: U27.B6 U46.3 | length 1755
  Top Layer w5: v1(860,1125.7) 835,1100.7 835,1045 850,1030 1130,1030 1145,1045 1390,1045 1425,1010 1690,1010 1810,1130 1905,1130 v1(1935,1100)
  Bottom Layer w5: v1(860,1125.7) U46.3@890.23,1125.7 ; v1(1935,1100) 1940,1100 1959.7,1119.7 1959.7,1234.96 1960,1235.26 1960,1236.82 2003.72,1280.54 2003.72,1306.5 2011.01,1313.79 2011.01,1314.01 2065.62,1368.62 2065.62,1466.78 U27.B6@2050.86,1481.54
UCPD_SNK: Q3.5 Q3.6 R209.1 SB46.2 | length 258.7
  Bottom Layer w20: 900.19,1584.8 Q3.5@921.01,1584.8 ; 921.01,1552.17 Q3.5@921.01,1584.8 ; 921.01,1617.43 Q3.5@921.01,1584.8 ; 941.83,1584.8 Q3.5@921.01,1584.8 ; 950.19,1584.8 Q3.6@971.01,1584.8 ; 971.01,1552.17 Q3.6@971.01,1584.8 ; 971.38,1683.02 971.38,1650 971.01,1649.63 Q3.6@971.01,1584.8
UCPD_SOURCE1: C196.1 Q4.5 Q4.6 SB48.2 | length 114.9
  Bottom Layer w20: 650,1552.68 Q4.5@650,1585.31 670.82,1585.31 ; 679.18,1585.31 Q4.6@700,1585.31 700,1552.68 ; 693.36,1670 SB48.2@701.38,1670
USB1_CN_HS_N: CN18.A7 CN18.B7 U51.2 | length 590.9
  Top Layer w6.1: v1(280,1055) 281.04,1055 296.54,1070.5 384.59,1070.5 430.09,1025 494.74,1025 515,1045.26 515,1073.62 500.12,1088.5 476.5,1088.5 v1(470,1095)
  Bottom Layer w6.1: CN18.B7@248.47,1064.25 269.71,1064.25 270.91,1063.05 271.95,1063.05 v1(280,1055) ; CN18.A7@315.4,1093.78 332.23,1093.78 334.57,1091.43 369.78,1091.43 373.71,1087.5 462.5,1087.5 v1(470,1095) 475,1090 U51.2@512.33,1090
USB1_CN_HS_P: CN18.A6 CN18.B6 U51.1 | length 587.4
  Top Layer w6.1: v1(280,1085) 280.5,1085.5 299.94,1085.5 308.74,1094.3 320.74,1094.3 329.54,1085.5 345.37,1085.5 354.17,1094.3 366.17,1094.3 374.97,1085.5 390.8,1085.5 399.43,1076.87 408.64,1076.87 416.75,1084.98 425.39,1084.98 431.49,1078.88 431.49,1070.52 423.68,1062.71 423.68,1052.62 436.3,1040 443.1,1040 451.9,1048.8 463.9,1048.8 472.7,1040 488.53,1040 500,1051.47 500,1067.4 493.9,1073.5 476.5,1073.5 v1(470,1067)
  Bottom Layer w6.1: CN18.B6@248.47,1083.93 249.54,1085 v1(280,1085) ; CN18.A6@315.4,1074.09 332.23,1074.09 334.57,1076.43 363.57,1076.43 367.5,1072.5 464.5,1072.5 v1(470,1067) 478,1075 511.58,1075 U51.1@512.33,1074.25
USB2_FAULT: R211.1 U47.3 | length 63
  Bottom Layer w20: U47.3@834.69,1897.91 842.28,1897.91 862.28,1917.91 R211.1@862.28,1945
USB_D1CONN_N: CN17.2 U49.2 | length 702.9
  Bottom Layer w6.1: CN17.2@460,1971.26 432.26,1999 403.78,1999 385.65,2017.13 385.65,2184.65 431.6,2230.6 514.52,2230.6 554.65,2190.47 554.65,2032.95 569,2018.6 U49.2@628.53,2018.6
USB_D1CONN_P: CN17.3 U49.1 | length 705.8
  Bottom Layer w6.1: CN17.3@460,2050 460,2039 435,2014 410,2014 400.65,2023.35 400.65,2045.35 409.45,2054.15 409.45,2066.15 400.65,2074.95 400.65,2086.95 409.45,2095.75 409.45,2107.75 400.65,2116.55 400.65,2128.55 409.45,2137.35 409.45,2149.35 400.65,2158.15 400.65,2178.43 437.82,2215.6 507,2215.6 ; 507.65,2216.25 539.65,2184.25 539.65,2172.25 530.85,2163.45 530.85,2151.45 539.65,2142.65 539.65,2130.65 530.85,2121.85 530.85,2109.85 539.65,2101.05 539.65,2089.05 530.85,2080.25 530.85,2068.25 539.65,2059.45 539.65,2026.73 562.78,2003.6 U49.1@627.98,2003.6
VBAT: C28.2 SB4.2 U27.E1 | length 129.5
  Top Layer w10: SB4.2@1816.62,1619 1819.65,1615.97 C28.2@1819.65,1580 1848,1580 v2(1852,1576) ; 1834,1609 1834,1620
  Bottom Layer w10: v2(1852,1576) 1852,1578 1853.97,1576.03 U27.E1@1893.38,1576.03
VBUS1: C197.2 CN18.A4 CN18.A9 CN18.B4 CN18.B9 R7.2 R152.2 R193.1 R213.1 U46.9 U50.1 | length 4370.5
  Top Layer w10: v1(1003.78,1245.41) 992,1257.19 992,1332.51 1011.48,1351.99 1011.99,1351.99 1013.56,1353.56 R7.2@1013.56,1415
  Top Layer w20: v1(455,1300) 455,1305 470,1320 v1(470,1330) 470,1585 565,1680 565,2435 725,2595 1290,2595 1375,2680 1548.23,2680 1554.23,2674 1604.7,2674 1645.6,2714.9 v1(1850,2714.9)
  L3_SIG w20: v1(1850,2714.9) 1955,2609.9 1955,2470 1990,2435 v1(2190,2435)
  Bottom Layer w10: U46.9@985.7,1201.49 985.69,1225.69 1003.78,1243.78 v1(1003.78,1245.41)
  Bottom Layer w11: CN18.B9@248.47,1024.88 v1(284.88,1024.88) 294.72,1034.72 CN18.A4@315.4,1034.72 340.28,1034.72 v1(345,1030) ; CN18.B4@248.47,1123.31 265.68,1123.31 280,1137.63 v1(280,1145) 291.85,1133.15 CN18.A9@315.4,1133.15 338.15,1133.15 v1(345,1140)
  Bottom Layer w20: v1(345,1030) 355,1020 355,1019.64 369.64,1005 370,1005 375,1000 v1(460,1000) ; v1(345,1140) 385,1140 C197.2@414.25,1169.25 ; C197.2@412,1169.25 C197.2@414.25,1169.25 ; C197.2@432.62,1143.71 C197.2@432.62,1169.25 ; 435.9,1270.9 435,1270 440,1270 ; R213.1@507.72,1375 507.72,1332.72 v1@475,1300 ; v1(510,1300) v1(485,1300) v1@475,1300 ; v1(1125,1375) 1125,1325 1147.72,1302.28 R193.1@1147.72,1214 R193.1@1150.72,1217 ; R152.2@2160.44,2435 v1(2190,2435) ; C197.2@414.25,1169.25 C197.2@432.62,1187.62 ; C197.2@414.25,1169.25 C197.2@426.72,1169.25 C197.2@432.62,1169.25 ; C197.2@432.62,1169.25 C197.2@432.62,1187.62 ; C197.2@432.62,1187.62 432.62,1262.62 440,1270 ; 440,1270 445,1270 458.78,1283.78 ; 440,1270 453.78,1283.78 458.78,1283.78 ; 458.78,1283.78 v1@475,1300
  other v1: 1100,1375 1101,1402 1126,1402
VBUS2: C194.1 C195.2 CN17.1 U47.1 U48.1 | length 219.4
  Bottom Layer w20: 418.51,1872.83 CN17.1@460,1872.83 ; 460,1831.34 CN17.1@460,1872.83 ; 460,1914.32 CN17.1@460,1872.83 ; 501.49,1872.83 CN17.1@460,1872.83 ; 801.07,1823.11 U47.1@834.69,1823.11 834.68,1803.28
VBUS_STLK: C120.1 C125.2 C132.2 CN6.A4 CN6.A9 CN6.B4 CN6.B9 D1.1 U16.1 U18.5 U20.3 U20.4 | length 1318
  Top Layer w20: v1(4690,1660) 5170,1660 v1(5365,1465)
  Bottom Layer w10: U20.3@4595.83,397.87 4595.82,415.82 4605,425 ; 4615,425 4615.51,424.49 U20.4@4615.51,397.87
  Bottom Layer w11: 5555,1161.96 CN6.A9@5585.95,1161.96 5625.83,1161.96 5635.67,1171.81 CN6.B4@5652.88,1171.81 ; v1@5556.35,1265.11 5561.07,1260.39 CN6.A4@5585.95,1260.39 5606.63,1260.39 v1(5616.47,1270.23) CN6.B9@5652.88,1270.23
  Bottom Layer w20: 4610.95,452.28 C132.2@4630,452.28 ; 4630,434.22 C132.2@4630,452.28 ; 4649.05,452.28 C132.2@4630,452.28 ; D1.1@4670.51,1589.14 4670.51,1640.51 v1(4690,1660) ; U18.5@4890,395.71 U18.5@4892.41,393.31 ; v1(5440,1387.01) 5497.72,1387.01 v1(5497.87,1387.16) ; C120.1@5512.72,1295 5522.01,1295 v1(5551.9,1265.11) v1@5556.35,1265.11 ; v1(5535,1135) v1(5535,1161.96) 5555,1161.96
  other v1: 4956.26,395.26 4926.54,396.54 4955.72,420.72 4926,422 4660,427 4689,427 4721,427 4957,451 4927.28,452.28 4659,455 4690,455 4722,455 5620,1160 5550,1290 5468,1387
VDD1V8: L4.1 L8.1 R21.2 | length 98.2
  Top Layer w4: 1523,1608 1524,1609 1524,1617
  Top Layer w20: v1(1756,1671) 1756,1707.5 L4.1@1760,1703.5 1771.5,1703.5 1785,1690 v1(1785,1674)
  other v1: 1529,1651 1555,1652 1581,1652 1530,1681 1558,1681 1582,1682
VDD3V3: C81.1 C189.2 CN3.50 CN8.2 CN8.4 LD1.1 LD2.1 LD8.1 LD10.1 R131.2 R136.2 R145.1 R159.1 R212.1 SB3.1 SB19.1 SB38.1 SB45.1 TP16.1 U45.7 U45.8 U46.2 | length 3637
  Top Layer w20: LD1.1@119.53,735 v1(119.53,780) ; LD2.1@182.13,735 v1(182.12,780) ; 987.73,3461.98 SB3.1@987.73,3475 ; 987.73,3488.02 SB3.1@987.73,3475 ; v1(987.72,3507.28) SB3.1@987.73,3475 ; v1(1015,3475) SB3.1@987.73,3475 ; CN3.50@2352.87,2676.22 2350,2679.09 C81.1@2350,2764.56 v1(2389.56,2764.56)
  L3_SIG w20: v1(3987.99,2957.01) 4150.98,3120 4865.5,3120 v1(5016.4,3270.9)
  Bottom Layer w7: 1048.15,2312.97 1048.24,2313.06 U45.7@1071.89,2313.06 U45.8@1071.89,2328.81
  Bottom Layer w10: v1(857.5,1092.5) 871.01,1106.01 U46.2@890.23,1106.01 ; 1050,2330 1051.19,2328.81 U45.8@1071.89,2328.81
  Bottom Layer w20: v1(190,1610) LD10.1@230.48,1610 ; R212.1@540,1517.72 v1(540,1565) ; LD8.1@1009.53,1950 v1(1045,1950) ; 1022.56,2314.46 C189.2@1022.56,2340 ; 1022.56,2365.54 C189.2@1022.56,2340 ; 1043.18,2340 C189.2@1022.56,2340 ; 1805,765 v1(1875,765) ; v1(1900.55,740) 1900.55,905 1926.1,930.55 R159.1@1981.1,930.55 ; R145.1@2377.56,945 v1(2415,945) ; v1(2389.56,2764.56) 2398.86,2764.56 2439.9,2805.6 2439.9,3230.1 2400,3270 2400,3635 SB45.1@2439.9,3674.9 2427.1,3674.9 ; 2402,3700 2402,3707.2 2404.9,3710.1 ; v1@2404.9,3909.9 v1(2405,3910) ; R131.2@3948.23,2957.01 v1(3987.99,2957.01) ; v1(5150,3035) CN8.2@5237.5,3035 ; v1(5157,2835) CN8.4@5237.5,2835 ; v1(5361.18,753.79) SB19.1@5397.38,753.79
  Bottom Layer w35: 2402,3700 2427.1,3674.9
  Bottom Layer w40: 2404.9,3710.1 v1@2404.9,3909.9 ; v1(2405,3910) v1(2405,3952)
  other v1: 3431.1,922.7 3461.1,922.7 3430,950 3460,950 1020,2390 1045,2390 1070,2390 1020,2420 1045,2420 1070,2420 990,3550 1025,3550
VDD_AUDIO: C147.2 C148.2 C149.2 C150.2 SB37.2 SB40.1 U34.6 U34.7 U34.23 | length 1624.4
  Top Layer w20: v1(1870,707.64) 1902.36,707.64 2010,600 2158.27,600 v1(2193.27,565) 2232.99,565 2291.39,506.6 2291.39,467.66 v1(2309.05,450) 2304.6,450 2266.6,412 2157.64,412 2050,304.36 2050,268.76 v1(2025,243.76) 1983.76,285 v1(1945,285)
  Bottom Layer w7: U34.23@2059.02,483.76 2059.02,505.02 2069,515
  Bottom Layer w8: C149.2@1995,250 1995,245.5 1996.02,246.52 1996.02,250 U34.6@1996.02,332.18
  Bottom Layer w9: U34.7@1980.28,332.18 1980.28,272.98 1968.8,261.5 C148.2@1945,261.5 ; C148.2@1945,261.5 1945.65,260.85 C148.2@1945.65,254.82 1945,255.46 C148.2@1945,261.5
  Bottom Layer w15: 2069,515 2079,525 2140,525 2150,535 2150,560 C147.2@2155,565 ; v1(2309.05,450) C150.2@2309.05,487.97
  Bottom Layer w20: 1870,669.37 v1(1870,707.64) ; C148.2@1945,261.5 v1(1945,285) ; C149.2@1996.02,250 2018.76,250 v1(2025,243.76) ; C147.2@2155,565 v1(2193.27,565) ; SB37.2@2309.07,412.65 v1@2309.06,449.99
VDD_CAM: C161.2 CN14.22 R221.1 R222.1 SB45.2 SB53.2 | length 1258.2
  L3_SIG w40: v1(1769.41,3950.59) 1769.41,3915.59 v1(2009.6,3675.4) 2055,3630 v1(2500,3630)
  Bottom Layer w12: 1903.28,3991 1919.61,4007.33 CN14.22@1919.61,4030.71
  Bottom Layer w15: 1836,3950.59 1857.13,3950.59 C161.2@1860,3947.71
  Bottom Layer w20: C161.2@1860,3947.71 1903.28,3991 ; R222.1@1954.02,3764.57 R221.1@2005,3764.57 2005,3680 v1(2009.6,3675.4)
  Bottom Layer w40: v1(1769.51,3917.79) 1769.41,3917.89 v1(1769.41,3950.59) 1836,3950.59
  other v1: 2471,3629
VDD_ETH: L1.2 L2.2 R207.1 SB3.2 | length 235.8
  Top Layer w20: 784.73,3260 L1.2@808.51,3260 ; 808.5,3233.28 L1.2@808.51,3260 ; 808.5,3286.72 L1.2@808.51,3260 ; 919.73,3405 L2.2@943.51,3405 ; 936.32,3475 SB3.2@949.35,3475 ; 943.5,3378.28 L2.2@943.51,3405 ; 943.5,3431.72 L2.2@943.51,3405 ; 949.34,3461.98 SB3.2@949.35,3475 ; 949.34,3488.02 SB3.2@949.35,3475
  Bottom Layer w20: R207.1@935,3282.72 v1(935,3325)
VDD_HEXASPI_M: C141.2 C142.2 C143.2 C144.2 R138.2 SB35.2 U26.D1 U26.E4 | length 484.5
  Bottom Layer w15: U26.E4@2901.14,1530.9 2901.14,1409.92 C144.2@2893.23,1402.01 2893.23,1358.85 C143.2@2903.07,1349.01 ; U26.D1@3019.25,1570.27 3032.52,1557 3099.72,1557 C142.2@3115,1572.28 3149.68,1572.28 C141.2@3160.51,1561.45
  Bottom Layer w20: C143.2@2903.07,1349.01 v1(2940.99,1349.01) ; R138.2@3152.72,1680 v1(3190,1680) ; 3160,1798.69 SB35.2@3160,1785.67 3173.02,1785.67 ; v1(3160.51,1525) C141.2@3160.51,1561.45
  other v1: 3200,1780 3225,1800
VDD_MIC: C117.2 C118.2 C119.2 CN5.2 CN5.12 CN5.19 R105.2 R106.1 SB19.2 U13.5 U14.5 | length 394.2
  Bottom Layer w10: U13.5@5536.68,879.3 5586.87,879.3 C119.2@5589.67,876.51
  Bottom Layer w12: U14.5@5503.84,771.35 5503.84,756.16 5510,750 5560,750 5571.51,761.51 C117.2@5589.67,761.51
  Bottom Layer w20: v1(5362.84,792.18) SB19.2@5397.38,792.18 ; v1(5398.68,838.02) R106.1@5398.68,875.28 ; v1(5548.68,673.25) R105.2@5548.68,723 ; v1(5561.18,845.52) 5589.66,874 C119.2@5589.67,876.51 ; v1(5589.66,732.04) C117.2@5589.67,761.51 ; C118.2@5589.67,801.51 5589.66,809 v1(5611.18,830.52)
VDD_OCTOSPI_M: C84.2 C87.2 C88.2 C89.2 C90.2 C91.2 R139.2 R140.2 R142.2 SB36.2 U25.B4 U25.D1 U25.E4 | length 425.6
  Top Layer w15: C84.2@2808,2097.56 2810.7,2100.26 v1(2849.89,2100.26) 2877.43,2072.72 C87.2@2885,2072.72 ; C89.2@2997.72,1960 3001.76,1964.04 v1(3001.76,1987.76) ; v1(3001.76,2139.63) 3002.28,2140.15 C90.2@3002.29,2170
  Top Layer w20: C88.2@3007.56,1900 v1(3035.16,1900) ; v1(3092.44,2120) C91.2@3092.45,2160
  Bottom Layer w10: v1(2849.89,2100.26) U25.D1@2866.77,2083.38 ; U25.B4@2984.88,2004.64 v1(3001.76,1987.76) ; U25.E4@2984.88,2122.75 v1(3001.76,2139.63)
  Bottom Layer w15: R139.2@3135.51,1999.73 v1(3135.51,2030)
  Bottom Layer w20: v1(2742.28,2102.72) R142.2@2780,2102.72 ; v1(3040.52,1800.52) R140.2@3040.52,1830.27 ; 3076.98,1785.67 SB36.2@3090,1785.67 ; 3090,1798.69 SB36.2@3090,1785.67 ; 3103.02,1785.67 SB36.2@3090,1785.67
  other v1: 3070,1851 3075,1887.5 3102.95,1887.95
VDD_SD: C85.1 C86.2 C146.2 CN13.4 R146.2 U28.6 U32.3 | length 1490.7
  Top Layer w20: C86.2@2907.72,630 2912.56,625.16 C85.1@2912.56,580 2912.56,522.56 v1(2910,520)
  L3_SIG w20: v1(2277.01,724.49) 2301.5,700 2301.5,543.5 2370,475 2865,475 v1(2910,520)
  Bottom Layer w10: 2120,890 2135.3,905.3 U32.3@2135.3,913.19
  Bottom Layer w15: R146.2@2324.3,704.49 2331.42,711.62 U28.6@2331.42,756.18
  Bottom Layer w20: 2120,890 2120,805 2153.07,771.93 C146.2@2277.01,771.93 v1(2277.01,724.49) 2297.01,704.49 R146.2@2324.3,704.49 ; v1(2910,520) 2923.79,533.79 CN13.4@2923.79,602.35
VDDA1V8: C46.2 C47.2 C50.2 C54.2 C71.2 C74.2 C77.2 C78.2 C79.2 C80.2 R27.1 R143.2 R173.2 R179.2 SB35.1 SB36.1 SB37.1 TP17.1 U6.8 U7.8 U8.8 U27.C5 U27.L13 U27.L14 U27.M5 U27.M14 U27.M15 U27.N6 U27.N13 U27.P13 U27.R5 U32.1 | length 3257.9
  Top Layer w10: C46.2@2002.1,1904.57 2002.1,1880.02 v2(2004.81,1877.3) ; v2(2003.58,1812.22) 2005.42,1812.22 2018.94,1825.74 C47.2@2021.84,1825.74 ; v2(2033.83,1498.56) 2033.83,1496.48 C50.2@2052.66,1477.66 ; v1(2043,1306) 2046,1309 2046,1406 2060,1420 2060,1470.31 ; C50.2@2052.66,1479.73 C50.2@2052.66,1477.66 ; 2060,1473.32 2060,1470.31 ; v2(2065.2,1811.9) 2066.1,1811 2067.85,1811 2076.52,1802.33 C54.2@2082.35,1802.33 ; C71.2@2257.68,1847.64 2268.91,1858.89 2270.66,1858.89 v2(2286.98,1875.21) ; C74.2@2265.83,1765 2270.83,1770 2276.32,1770 2284.32,1778 2287,1778 v2(2288,1779) ; C77.2@2271,1822.83 2272,1823.83 2272,1828.73 v2(2286.98,1843.71) ; v2(2289.66,1813.6) 2290.86,1813.6 2303.09,1825.83 C79.2@2309,1825.83 ; C78.2@2302.68,1762.64 2302.67,1764.86 v2(2318.51,1780.7) ; C80.2@2331,1825.83 2336.39,1825.83 v2(2350.02,1812.2) ; C50.2@2052.66,1477.66 2060,1470.31
  Top Layer w15: v1(4081.61,3245) U6.8@4081.61,3293.66 ; v1(4351.61,3245) U7.8@4351.61,3293.66 ; v1(4621.61,3245) U8.8@4621.61,3293.66
  Top Layer w20: R27.1@1940.51,2164.57 1940.51,2201.96 v1(1941.55,2203) ; v1(2195,885) 2203.19,876.81 2203.19,736.81 2365,575 2365,442.65 v1(2395,412.65)
  L3_SIG w20: v1(1400,1380) 1929,851 v1(1982.5,851) 2161,851 v1(2195,885)
  Bottom Layer w10: v2(2003.58,1812.22) 2019.3,1796.5 U27.M5@2019.36,1796.5 ; v2(2004.81,1877.3) 2005.67,1877.3 U27.R5@2019.36,1890.99 ; 2010,1255 2021.22,1266.22 2021.22,1291.22 2036,1306 v1(2043,1306) ; U27.C5@2019.36,1513.03 v2(2033.83,1498.56) ; U27.N6@2050.86,1827.99 2065.2,1813.65 v2(2065.2,1811.9) ; U32.1@2174.67,913.19 2195,892.86 v1(2195,885) ; U27.L13@2271.33,1765 2284.33,1778 2287,1778 v2(2288,1779) ; U27.N13@2271.33,1827.99 2271.33,1828.06 v2(2286.98,1843.71) ; U27.P13@2271.33,1859.49 2271.33,1859.56 v2(2286.98,1875.21) ; v2(2289.66,1813.6) 2289.66,1811.34 2291,1810 2291,1808.32 U27.M14@2302.83,1796.5 ; U27.L14@2302.83,1765 v2(2318.51,1780.7) ; U27.M15@2334.33,1796.5 v2(2350.02,1812.2)
  Bottom Layer w20: R179.2@1322.56,2495 R179.2@1322.56,2502.71 ; v1(1519,1569) 1545,1595 R173.2@1572.45,1595 ; v1(1982.5,851) 1981.1,852.4 2025,896.3 2025,1030 1981.1,1073.9 1981.1,1226.1 2010,1255 ; SB37.1@2347.45,412.65 v1(2395,412.65) 2396.45,414.1 R143.2@2450.58,414.1 ; 3076.98,1747.28 SB36.1@3090,1747.28 ; 3090,1734.26 SB36.1@3090,1747.28 ; 3103.02,1747.28 SB36.1@3090,1747.28 ; 3146.98,1747.28 SB35.1@3160,1747.28 ; 3160,1734.26 SB35.1@3160,1747.28 ; 3173.02,1747.28 SB35.1@3160,1747.28
  other v1: 3085,1710 3110,1710 1355,2460 1380,2460 1355,2490 1380,2490
VDDA1V8_AON: C36.2 R148.1 R163.2 TP15.1 U27.A1 | length 140.8
  Top Layer w10: v2@1875,1455.02 1885.02,1445 C36.2@1899.18,1445
  Bottom Layer w10: v2@1875,1455.02 1879.98,1450.04 U27.A1@1893.38,1450.04
  Bottom Layer w20: 1779.45,1006.39 R163.2@1779.45,1040 ; 1779.45,1073.61 R163.2@1779.45,1040 ; 1804.2,1040 R163.2@1779.45,1040
  other v1: 1815,1030 1840,1030 1815,1060 1840,1060
  other v2: 1874.95,1455.02
VDDA1V8PMU: C169.2 L8.2 R173.1 U27.G1 | length 316.5
  Bottom Layer w10: L8.2@1680,1575.63 1687.87,1583.5 ; 1680,1583.5 1687.87,1583.5 ; U27.G1@1893.38,1639.02 1864.02,1639.02 1832,1607 1742.59,1607 C169.2@1727,1591.41 1696.4,1591.41 ; 1687.87,1583.5 1688.49,1583.5 1696.4,1591.41 ; 1687.87,1583.5 1695.78,1591.41 1696.4,1591.41
  Bottom Layer w20: R173.1@1627.56,1595 1639.06,1583.5 1680,1583.5
VDDA18AON: C40.2 R148.2 U27.F6 | length 122.3
  Top Layer w10: v1(1925,1225) 1930.83,1230.83 C40.2@1955,1230.83
  Bottom Layer w10: v2(2035.09,1591.82) 2050.79,1607.52 U27.F6@2050.86,1607.52
  Bottom Layer w20: v1(1865,1110) 1865,1090 1895.55,1059.45 R148.2@1900,1059.45
VDDCORE: C44.2 C51.2 C57.2 C60.2 C61.2 C63.2 C65.2 C68.2 C69.2 C70.2 R22.1 R30.2 TP10.1 U27.L6 U27.L12 U27.M7 U27.M9 U27.M11 U27.N8 U27.N10 U27.N12 U27.P11 U27.R4 | length 616.1
  Top Layer w10: v2(1973,1908) 1973,1905.85 1987.8,1891.05 1987.8,1883.47 1987.81,1867.09 C44.2@1990.34,1864.56 ; C51.2@2052.35,1767.33 2064.68,1755 v2(2070,1755) ; v2(2090,1775) 2090,1760.83 C57.2@2095,1755.83 ; C60.2@2121.48,1758.51 2110,1769.99 2110,1792.64 v2(2129.63,1812.27) ; C61.2@2142.68,1857.64 2147.12,1857.65 v2(2161.06,1843.71) ; C63.2@2150,1760.83 2150,1769.78 v2(2161,1780.78) ; C65.2@2180,1760.83 2180,1768.23 v2(2192.55,1780.78) ; C70.2@2209,1760.83 2210,1761.83 2210,1766.68 v2(2224.02,1780.7) ; C68.2@2210.18,1860.66 2210.18,1861.4 v2(2223.99,1875.21) ; C69.2@2222.68,1812.64 2222.67,1842.35 v2(2224.02,1843.7)
  Top Layer w20: 1657.29,1927.56 R22.1@1685,1927.56 ; 1685,1948.18 R22.1@1685,1927.56 ; 1712.71,1927.56 R22.1@1685,1927.56
  Bottom Layer w10: v2(1973,1908) 1973,1905.85 U27.R4@1987.87,1890.99 ; U27.L6@2050.86,1765 2060.86,1755 v2(2070,1755) ; U27.M7@2082.35,1796.5 2082.35,1796.37 2090,1788.72 v2(2090,1775) ; U27.N8@2113.85,1827.99 2113.91,1827.99 v2(2129.63,1812.27) ; U27.M9@2145.35,1796.5 2145.34,1796.44 v2(2161,1780.78) ; v2(2161.06,1843.71) U27.N10@2176.84,1827.99 U27.N10@2176.84,1827.99 ; v2(2192.55,1780.78) U27.M11@2208.34,1796.5 U27.M11@2208.34,1796.5 ; U27.P11@2208.34,1859.49 2208.34,1859.56 v2(2223.99,1875.21) ; v2(2224.02,1780.7) 2239.72,1765 U27.L12@2239.84,1765 ; v2(2224.02,1843.7) 2239.73,1827.99 U27.N12@2239.84,1827.99
  other v1: 1672.4,2004 1647.3,2031 1672.3,2031 1647.3,2058.2 1672.3,2058.2 1980,2860 2005,2860 1980,2885 2005,2885 1980,2915 2005,2915
VDDIO: B2.1 B2.2 B4.1 B4.2 C55.2 C58.2 C66.2 C67.2 C72.2 C73.2 C75.2 C76.2 C152.2 CN1.1 CN10.1 LNK3.1 R5.2 R36.1 R38.1 R78.2 R149.1 R153.1 SB4.1 SW1.2 SW2.2 TP13.1 U27.E8 U27.F8 U27.G13 U27.H12 U27.H13 U27.J12 U27.J13 U27.K13 U32.5 | length 7431.6
  Top Layer w10: v2(2098.06,1591.78) 2120.54,1614.26 C58.2@2120.55,1622.43 ; v2(2098.06,1623.28) 2105.83,1631.05 C55.2@2105.83,1647 ; C66.2@2202.34,1655.01 2223.81,1655.01 v2(2224.02,1654.8) ; C67.2@2202.51,1688.01 2220,1705.5 v2(2220,1710) ; C72.2@2265.34,1643.01 2270.34,1638.01 2272.22,1638.01 v2(2286.97,1623.26) ; C73.2@2265.83,1725 2279.84,1725 v2(2284.92,1719.92) ; C75.2@2266.34,1699.01 2274.22,1699.01 v2(2286.97,1686.26) ; C76.2@2267.34,1670.01 2271.72,1670.01 v2(2286.97,1654.76)
  Top Layer w15: v2(1752.14,1583) 1752.14,1597.83 SB4.1@1773.32,1619
  Top Layer w20: v1(201.87,3790) CN1.1@245.02,3790 ; R5.2@477.72,3845 503,3845 v1(539,3881) ; R36.1@2245,1392.28 2245,1375 v1(2255,1365) ; v2(2304,1355) 2304,1391.28 R38.1@2305,1392.28 ; 3836.82,1490 R78.2@3857.45,1490 ; 3857.44,1462.29 R78.2@3857.45,1490 ; 3857.44,1517.71 R78.2@3857.45,1490 ; v1(5480,2750) B2.1@5569.77,2750 ; B4.1@5569.77,3250 v1(5655,3250) ; v1(5705,3248.74) B4.2@5790.24,3248.74 ; v1(5710,2750) 5827.92,2750 B2.2@5836.5,2758.58
  L3_SIG w20: v1(201.87,3790) 299,3790 390,3881 v1(539,3881) 539,3906 624,3991 1819,3991 1876,3934 2276,3934 2321,3889 2321,3858 2347,3832 2566,3832 2668,3934 3954,3934 4185,4165 5280,4165 5590,3855 SW2.2@5590,3735
  Bottom Layer w8: v1(4585,1306.14) LNK3.1@4690,1306.14
  Bottom Layer w10: v2(2098.06,1591.78) U27.E8@2113.85,1576.03 ; v2(2098.06,1623.28) U27.F8@2113.85,1607.52 ; C152.2@2145,982.28 2145,965 2154.99,955.01 U32.5@2154.99,936.81 ; v2(2220,1710) 2231.84,1710 U27.J12@2239.84,1702.01 ; v2(2224.02,1654.8) 2239.73,1670.51 U27.H12@2239.84,1670.51 ; U27.G13@2271.33,1639.02 2271.33,1638.9 v2(2286.97,1623.26) ; U27.H13@2271.33,1670.51 2271.33,1670.4 v2(2286.97,1654.76) ; U27.J13@2271.33,1702.01 2271.33,1701.9 v2(2286.97,1686.26) ; U27.K13@2271.33,1733.51 v2(2284.92,1719.92)
  Bottom Layer w20: v1(2110,1000) 2127.72,982.28 C152.2@2145,982.28 ; R153.1@2155,1232.28 2164,1223.28 v1(2164,1197) ; v1(2209,1176) 2209,1231.28 R149.1@2210,1232.28 ; CN10.1@3785.76,597.01 v1(3872.01,597.01)
  other v1: 3715,1400 3740,1400 3715,1435 3740,1435 3715,1470 3740,1470
VDDIO_SD: C59.2 C64.2 R73.2 R74.2 R75.2 R76.2 R77.2 U27.E9 U27.F9 U32.4 | length 295.6
  Top Layer w10: v2(2129.26,1559.95) 2140.46,1571.15 C59.2@2140.46,1577.74 ; v2(2160.6,1590.9) 2163.78,1590.9 C64.2@2177.35,1577.33
  Top Layer w20: R73.2@2740,840 v1(2740,872.28) ; R74.2@2795,840 v1(2795,872.28) ; R75.2@2960,839.72 v1(2960,872) ; R76.2@3002,838.72 v1(3002,871) ; R77.2@3049,838.72 v1(3049,871)
  Bottom Layer w10: v1(2095,945) 2103.19,936.81 U32.4@2135.3,936.81 ; v2(2129.26,1559.95) U27.E9@2145.35,1576.03 ; U27.F9@2145.35,1607.52 2158.2,1594.66 2158.2,1593.3 v2(2160.6,1590.9)
  other v1: 2065,945
VIN: C131.2 CN8.8 U21.3 | length 408.3
  Bottom Layer w20: 4507.56,2498.99 U21.3@4507.57,2539.49 ; 4507.56,2579.99 U21.3@4507.57,2539.49 ; 4545.11,2539.49 U21.3@4507.57,2539.49 ; 4579.42,2571.54 C131.2@4615,2571.53 ; 4615,2545.8 C131.2@4615,2571.53 ; 4615,2597.28 C131.2@4615,2571.53 ; 4650.58,2571.54 C131.2@4615,2571.53 ; 5182,2435 CN8.8@5237.52,2435 ; 5237.52,2406.98 CN8.8@5237.52,2435 ; 5237.52,2463.02 CN8.8@5237.52,2435 ; 5293.04,2435 CN8.8@5237.52,2435
VL_AUDIO: C159.2 SB38.2 SB39.1 U34.4 | length 1110.1
  Top Layer w20: v1(1740,630) 1740,599.68 1651.22,510.91 1651.22,341.22 1776.68,215.76 2055.76,215.76 2080,240 v1(2080,265.4)
  Bottom Layer w7: U34.4@2027.52,332.18 2027.52,307.48 2045,290 2045,275
  Bottom Layer w10: 2045,275 2045,257.28 C159.2@2055,247.28
  Bottom Layer w20: v1(1740,630) 1765,655 1800,655 SB38.2@1800,724.33 ; C159.2@2055,247.28 2061.88,247.28 2079.6,265 v1@2080,265
VREFP: C38.2 C39.2 C140.1 R27.2 R137.2 U27.U2 | length 2869.6
  Top Layer w12: v2(1924.81,1975) 1930,1975 1951.34,1996.34 1951.34,2098.62 R27.2@1940.51,2109.45
  Top Layer w15: R27.2@1940.51,2109.45 1980,2148.94 1980,2705 2445,3170 3395,3170 3515,3290 3640.98,3290 v1(3697.99,3347.01)
  Bottom Layer w10: v2(1924.81,1975) 1924.81,1954.04 U27.U2@1924.88,1953.98
  Bottom Layer w20: R137.2@3648.23,3297.01 C140.1@3648.23,3347.01 v1(3697.99,3347.01)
